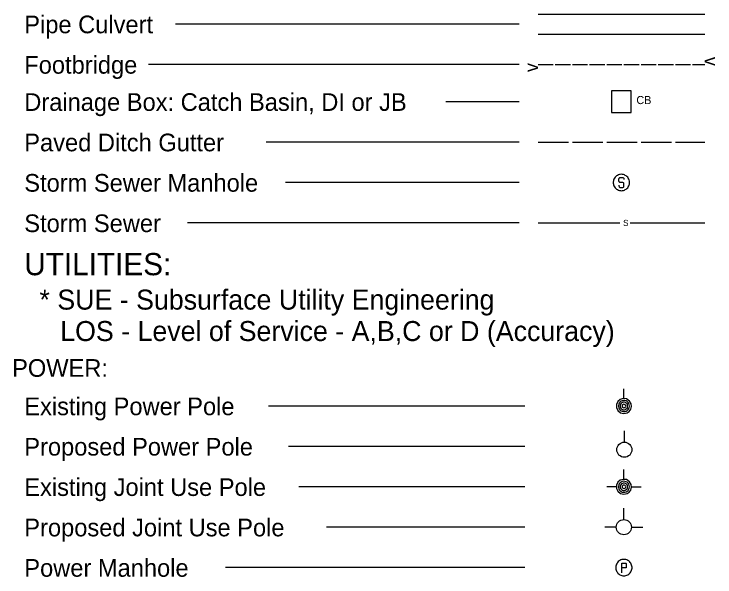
# Model space of a CAD drawing. Extents: x 2594871.4 to 2594905.1, y 784137.6 to 784159.6.
# Drawn here: x 2594889.98 to 2594896.79, y 784148.14 to 784153.61 of the extents above; entities that cross this region are included whole.
import ezdxf

# ---------------------------------------------------------------- set-up
doc = ezdxf.new("R2010")
doc.units = 0
doc.layers.add('Default', color=7, linetype='Continuous')

msp = doc.modelspace()

# ---------------------------------------------------------------- linework, layer by layer
at = {"layer": 'Default'}
for p, q in [((2594895.068, 784153.6117), (2594896.6863, 784153.6117)), ((2594894.8856, 784153.5137), (2594891.5473, 784153.5137)), ((2594895.068, 784153.4156), (2594896.6863, 784153.4156)), ((2594894.8856, 784153.1214), (2594891.2867, 784153.1214)), ((2594895.068, 784153.1214), (2594895.2151, 784153.1214)), ((2594895.2348, 784153.1214), (2594895.3819, 784153.1214)), ((2594895.4015, 784153.1214), (2594895.5486, 784153.1214)), ((2594895.5682, 784153.1214), (2594895.7153, 784153.1214)), ((2594895.735, 784153.1214), (2594895.8821, 784153.1214)), ((2594895.9017, 784153.1214), (2594896.0488, 784153.1214)), ((2594896.0684, 784153.1214), (2594896.2155, 784153.1214)), ((2594896.2351, 784153.1214), (2594896.3823, 784153.1214)), ((2594896.4019, 784153.1214), (2594896.549, 784153.1214)), ((2594896.5686, 784153.1214), (2594896.6863, 784153.1214)), ((2594894.8856, 784152.7597), (2594894.1737, 784152.7597)), ((2594894.8856, 784152.3674), (2594892.43, 784152.3674)), ((2594895.068, 784152.3674), (2594895.3623, 784152.3674)), ((2594895.4015, 784152.3674), (2594895.6957, 784152.3674)), ((2594895.735, 784152.3674), (2594896.0292, 784152.3674)), ((2594896.0684, 784152.3674), (2594896.3626, 784152.3674)), ((2594896.4019, 784152.3674), (2594896.6863, 784152.3674)), ((2594895.8536, 784151.9891), (2594895.8536, 784152.0101)), ((2594895.8676, 784152.0241), (2594895.8886, 784152.0241)), ((2594895.902, 784152.0101), (2594895.902, 784152.0031)), ((2594894.8856, 784151.9751), (2594892.6166, 784151.9751)), ((2594895.8536, 784151.9477), (2594895.8536, 784151.9407)), ((2594895.8886, 784151.9757), (2594895.8676, 784151.9757)), ((2594895.902, 784151.9407), (2594895.902, 784151.9623)), ((2594895.8676, 784151.9273), (2594895.8886, 784151.9273)), ((2594894.8856, 784151.5828), (2594891.6648, 784151.5828)), ((2594895.068, 784151.5828), (2594895.8629, 784151.5828)), ((2594895.961, 784151.5828), (2594896.6863, 784151.5828)), ((2594895.9017, 784149.8764), (2594895.9017, 784149.9705)), ((2594894.9403, 784149.804), (2594892.4518, 784149.804)), ((2594895.9059, 784149.4532), (2594895.9059, 784149.5635)), ((2594894.9403, 784149.4117), (2594892.6457, 784149.4117)), ((2594895.9017, 784149.0918), (2594895.9017, 784149.1859)), ((2594894.9403, 784149.0194), (2594892.7451, 784149.0194)), ((2594895.8293, 784149.0194), (2594895.7352, 784149.0194)), ((2594895.9741, 784149.0194), (2594896.0682, 784149.0194)), ((2594895.9017, 784148.7009), (2594895.9017, 784148.8112)), ((2594894.9403, 784148.6271), (2594893.0136, 784148.6271)), ((2594895.8281, 784148.6273), (2594895.7178, 784148.6273)), ((2594895.9752, 784148.6273), (2594896.0856, 784148.6273)), ((2594895.924, 784148.2711), (2594895.924, 784148.2373)), ((2594894.9403, 784148.2348), (2594892.0341, 784148.2348)), ((2594895.9176, 784148.231), (2594895.882, 784148.231))]:
    msp.add_line(p, q, dxfattribs=at)
for points in [[(2594895.7828, 784152.6555), (2594895.9713, 784152.6555), (2594895.9713, 784152.8642), (2594895.7828, 784152.8642)], [(2594895.9017, 784149.7316), (2594895.9321, 784149.7374), (2594895.9524, 784149.7519), (2594895.9683, 784149.7722), (2594895.9741, 784149.7997), (2594895.9712, 784149.8258), (2594895.9567, 784149.8518), (2594895.9278, 784149.8735), (2594895.8945, 784149.8764), (2594895.8655, 784149.8677), (2594895.8423, 784149.8474), (2594895.8308, 784149.82), (2594895.8308, 784149.7881), (2594895.8423, 784149.7606), (2594895.8684, 784149.7388)], [(2594895.9017, 784148.947), (2594895.9321, 784148.9528), (2594895.9524, 784148.9673), (2594895.9683, 784148.9876), (2594895.9741, 784149.0151), (2594895.9712, 784149.0411), (2594895.9567, 784149.0672), (2594895.9278, 784149.0889), (2594895.8945, 784149.0918), (2594895.8655, 784149.0831), (2594895.8423, 784149.0628), (2594895.8308, 784149.0353), (2594895.8308, 784149.0035), (2594895.8423, 784148.976), (2594895.8684, 784148.9542)]]:
    msp.add_lwpolyline(points, close=True, dxfattribs=at)
for points in [[(2594895.8772, 784152.0547), (2594895.867, 784152.0541), (2594895.8574, 784152.0522), (2594895.8479, 784152.049), (2594895.8389, 784152.0445), (2594895.8307, 784152.0394), (2594895.823, 784152.0331), (2594895.816, 784152.0254), (2594895.8103, 784152.0178), (2594895.8052, 784152.0089), (2594895.802, 784151.9993), (2594895.7994, 784151.9897), (2594895.7982, 784151.9802), (2594895.7982, 784151.97), (2594895.7994, 784151.9604), (2594895.802, 784151.9503), (2594895.8052, 784151.9413), (2594895.8103, 784151.9324), (2594895.816, 784151.9248), (2594895.823, 784151.9171), (2594895.8307, 784151.9107), (2594895.8389, 784151.9057), (2594895.8479, 784151.9012), (2594895.8574, 784151.898), (2594895.8676, 784151.8961), (2594895.8772, 784151.8955), (2594895.8874, 784151.8961), (2594895.8969, 784151.898), (2594895.9065, 784151.9012), (2594895.9154, 784151.9057), (2594895.9237, 784151.9107), (2594895.9313, 784151.9171), (2594895.9383, 784151.9248), (2594895.9441, 784151.9324), (2594895.9492, 784151.9413), (2594895.9524, 784151.9509), (2594895.9549, 784151.9604), (2594895.9562, 784151.97), (2594895.9562, 784151.9802), (2594895.9549, 784151.9897), (2594895.9524, 784151.9999), (2594895.9492, 784152.0089), (2594895.9441, 784152.0178), (2594895.9383, 784152.0254), (2594895.9313, 784152.0331), (2594895.9237, 784152.0394), (2594895.9154, 784152.0445), (2594895.9065, 784152.049), (2594895.8969, 784152.0522), (2594895.8867, 784152.0541), (2594895.8772, 784152.0547)], [(2594895.8536, 784152.0101), (2594895.8549, 784152.0146), (2594895.8568, 784152.0184), (2594895.8593, 784152.021), (2594895.8632, 784152.0229), (2594895.8676, 784152.0241)], [(2594895.8886, 784152.0241), (2594895.8925, 784152.0229), (2594895.8963, 784152.021), (2594895.8995, 784152.0184), (2594895.9014, 784152.0146), (2594895.902, 784152.0101)], [(2594895.8676, 784151.9757), (2594895.8632, 784151.9764), (2594895.8593, 784151.9783), (2594895.8568, 784151.9815), (2594895.8549, 784151.9853), (2594895.8536, 784151.9891)], [(2594895.8536, 784151.9413), (2594895.8549, 784151.9369), (2594895.8568, 784151.9331), (2594895.8593, 784151.9299), (2594895.8632, 784151.928), (2594895.8676, 784151.9273)], [(2594895.902, 784151.9617), (2594895.9014, 784151.9662), (2594895.8995, 784151.97), (2594895.8963, 784151.9732), (2594895.8925, 784151.9751), (2594895.8886, 784151.9757)], [(2594895.8886, 784151.9273), (2594895.8925, 784151.928), (2594895.8963, 784151.9299), (2594895.8995, 784151.9331), (2594895.9014, 784151.9369), (2594895.902, 784151.9413)], [(2594895.9553, 784149.804), (2594895.9538, 784149.817), (2594895.9495, 784149.8286), (2594895.9422, 784149.8388), (2594895.9335, 784149.8474), (2594895.9234, 784149.8533), (2594895.9104, 784149.8562), (2594895.8988, 784149.8576), (2594895.8857, 784149.8547), (2594895.8742, 784149.8504), (2594895.8655, 784149.8431), (2594895.8568, 784149.833), (2594895.851, 784149.8228), (2594895.8481, 784149.8098), (2594895.8481, 784149.7982), (2594895.851, 784149.7852), (2594895.8568, 784149.7751), (2594895.8655, 784149.7649), (2594895.8742, 784149.7577), (2594895.8857, 784149.7533), (2594895.8988, 784149.7504), (2594895.9104, 784149.7519), (2594895.9234, 784149.7548), (2594895.9335, 784149.7606), (2594895.9422, 784149.7693), (2594895.9495, 784149.7794), (2594895.9538, 784149.791), (2594895.9553, 784149.804)], [(2594895.9379, 784149.804), (2594895.9364, 784149.8142), (2594895.9321, 784149.8243), (2594895.9249, 784149.8315), (2594895.9162, 784149.8373), (2594895.9075, 784149.8402), (2594895.8959, 784149.8402), (2594895.8872, 784149.8373), (2594895.8785, 784149.8315), (2594895.8713, 784149.8243), (2594895.8669, 784149.8142), (2594895.8655, 784149.804), (2594895.8669, 784149.7939), (2594895.8713, 784149.7838), (2594895.8785, 784149.7765), (2594895.8872, 784149.7707), (2594895.8959, 784149.7678), (2594895.9075, 784149.7678), (2594895.9162, 784149.7707), (2594895.9249, 784149.7765), (2594895.9321, 784149.7838), (2594895.9364, 784149.7939), (2594895.9379, 784149.804)], [(2594895.9191, 784149.804), (2594895.9176, 784149.8113), (2594895.9133, 784149.817), (2594895.9075, 784149.82), (2594895.9002, 784149.8214), (2594895.893, 784149.8185), (2594895.8872, 784149.8142), (2594895.8843, 784149.8069), (2594895.8843, 784149.8011), (2594895.8872, 784149.7939), (2594895.893, 784149.7895), (2594895.9002, 784149.7867), (2594895.9075, 784149.7881), (2594895.9133, 784149.791), (2594895.9176, 784149.7968), (2594895.9191, 784149.804)], [(2594895.9553, 784149.0194), (2594895.9538, 784149.0324), (2594895.9495, 784149.044), (2594895.9422, 784149.0542), (2594895.9335, 784149.0628), (2594895.9234, 784149.0687), (2594895.9104, 784149.0715), (2594895.8988, 784149.073), (2594895.8857, 784149.0701), (2594895.8742, 784149.0657), (2594895.8655, 784149.0585), (2594895.8568, 784149.0484), (2594895.851, 784149.0382), (2594895.8481, 784149.0252), (2594895.8481, 784149.0136), (2594895.851, 784149.0006), (2594895.8568, 784148.9905), (2594895.8655, 784148.9803), (2594895.8742, 784148.9731), (2594895.8857, 784148.9687), (2594895.8988, 784148.9658), (2594895.9104, 784148.9673), (2594895.9234, 784148.9702), (2594895.9335, 784148.976), (2594895.9422, 784148.9847), (2594895.9495, 784148.9948), (2594895.9538, 784149.0064), (2594895.9553, 784149.0194)], [(2594895.9379, 784149.0194), (2594895.9364, 784149.0296), (2594895.9321, 784149.0397), (2594895.9249, 784149.0469), (2594895.9162, 784149.0527), (2594895.9075, 784149.0556), (2594895.8959, 784149.0556), (2594895.8872, 784149.0527), (2594895.8785, 784149.0469), (2594895.8713, 784149.0397), (2594895.8669, 784149.0296), (2594895.8655, 784149.0194), (2594895.8669, 784149.0093), (2594895.8713, 784148.9992), (2594895.8785, 784148.9919), (2594895.8872, 784148.9861), (2594895.8959, 784148.9832), (2594895.9075, 784148.9832), (2594895.9162, 784148.9861), (2594895.9249, 784148.9919), (2594895.9321, 784148.9992), (2594895.9364, 784149.0093), (2594895.9379, 784149.0194)], [(2594895.9191, 784149.0194), (2594895.9176, 784149.0266), (2594895.9133, 784149.0324), (2594895.9075, 784149.0353), (2594895.9002, 784149.0368), (2594895.893, 784149.0339), (2594895.8872, 784149.0296), (2594895.8843, 784149.0223), (2594895.8843, 784149.0165), (2594895.8872, 784149.0093), (2594895.893, 784149.0049), (2594895.9002, 784149.002), (2594895.9075, 784149.0035), (2594895.9133, 784149.0064), (2594895.9176, 784149.0122), (2594895.9191, 784149.0194)], [(2594895.9017, 784148.3144), (2594895.8915, 784148.3138), (2594895.882, 784148.3119), (2594895.8724, 784148.3087), (2594895.8635, 784148.3042), (2594895.8552, 784148.2991), (2594895.8475, 784148.2928), (2594895.8405, 784148.2851), (2594895.8348, 784148.2775), (2594895.8297, 784148.2686), (2594895.8265, 784148.259), (2594895.824, 784148.2494), (2594895.8227, 784148.2399), (2594895.8227, 784148.2297), (2594895.824, 784148.2201), (2594895.8265, 784148.21), (2594895.8297, 784148.201), (2594895.8348, 784148.1921), (2594895.8405, 784148.1845), (2594895.8475, 784148.1768), (2594895.8552, 784148.1705), (2594895.8635, 784148.1654), (2594895.8724, 784148.1609), (2594895.882, 784148.1577), (2594895.8921, 784148.1558), (2594895.9017, 784148.1552), (2594895.9119, 784148.1558), (2594895.9214, 784148.1577), (2594895.931, 784148.1609), (2594895.9399, 784148.1654), (2594895.9482, 784148.1705), (2594895.9558, 784148.1768), (2594895.9629, 784148.1845), (2594895.9686, 784148.1921), (2594895.9737, 784148.201), (2594895.9769, 784148.2106), (2594895.9794, 784148.2201), (2594895.9807, 784148.2297), (2594895.9807, 784148.2399), (2594895.9794, 784148.2494), (2594895.9769, 784148.2596), (2594895.9737, 784148.2686), (2594895.9686, 784148.2775), (2594895.9629, 784148.2851), (2594895.9558, 784148.2928), (2594895.9482, 784148.2991), (2594895.9399, 784148.3042), (2594895.931, 784148.3087), (2594895.9214, 784148.3119), (2594895.9112, 784148.3138), (2594895.9017, 784148.3144)], [(2594895.882, 784148.1838), (2594895.882, 784148.231), (2594895.882, 784148.2775), (2594895.9176, 784148.2775)], [(2594895.9176, 784148.2775), (2594895.9202, 784148.2768), (2594895.9221, 784148.2756), (2594895.9234, 784148.2737), (2594895.924, 784148.2711)], [(2594895.924, 784148.2373), (2594895.9234, 784148.2348), (2594895.9221, 784148.2329), (2594895.9202, 784148.2316), (2594895.9176, 784148.231)]]:
    msp.add_lwpolyline(points, dxfattribs=at)
for centre in [(2594895.9059, 784149.3796), (2594895.9017, 784148.6271)]:
    msp.add_circle(centre, 0.0736, dxfattribs=at)

# ---------------------------------------------------------------- texts
for s, height, rotation, p in [('Pipe Culvert', 0.171636, 360, (2594890.0806, 784153.4247)), ('Footbridge', 0.17164, 360, (2594890.0808, 784153.0323)), ('v', 0.1295, 270.24085, (2594896.6861, 784153.1947)), ('v', 0.1295, 89.75915, (2594895.0678, 784153.048)), ('Drainage Box: Catch Basin, DI or JB', 0.171636, 360, (2594890.0808, 784152.6707)), ('CB', 0.07846, 360, (2594896.0231, 784152.7367)), ('Paved Ditch Gutter', 0.171636, 360, (2594890.0808, 784152.2781)), ('Storm Sewer Manhole', 0.171636, 360, (2594890.0808, 784151.8858)), ('Storm Sewer', 0.171636, 360, (2594890.0808, 784151.4935)), ('S', 0.0588, 360, (2594895.8943, 784151.5534)), ('UTILITIES:', 0.21577, 360, (2594890.0806, 784151.0744)), ('* SUE - Subsurface Utility Engineering', 0.194193, 360, (2594890.2284, 784150.7405)), ('LOS - Level of Service - A,B,C or D (Accuracy) ', 0.194193, 360, (2594890.4298, 784150.4352)), ('POWER:', 0.17164, 360, (2594889.9624, 784150.0877)), ('Existing Power Pole', 0.171636, 360, (2594890.0808, 784149.715)), ('Proposed Power Pole', 0.171636, 360, (2594890.0808, 784149.3227)), ('Existing Joint Use Pole', 0.171636, 360, (2594890.0808, 784148.9306)), ('Proposed Joint Use Pole', 0.171636, 360, (2594890.0811, 784148.5381)), ('Power Manhole', 0.171636, 360, (2594890.0811, 784148.1458))]:
    msp.add_text(s, height=height, rotation=rotation, dxfattribs=at).set_placement(p)

doc.saveas('drawing.dxf')
